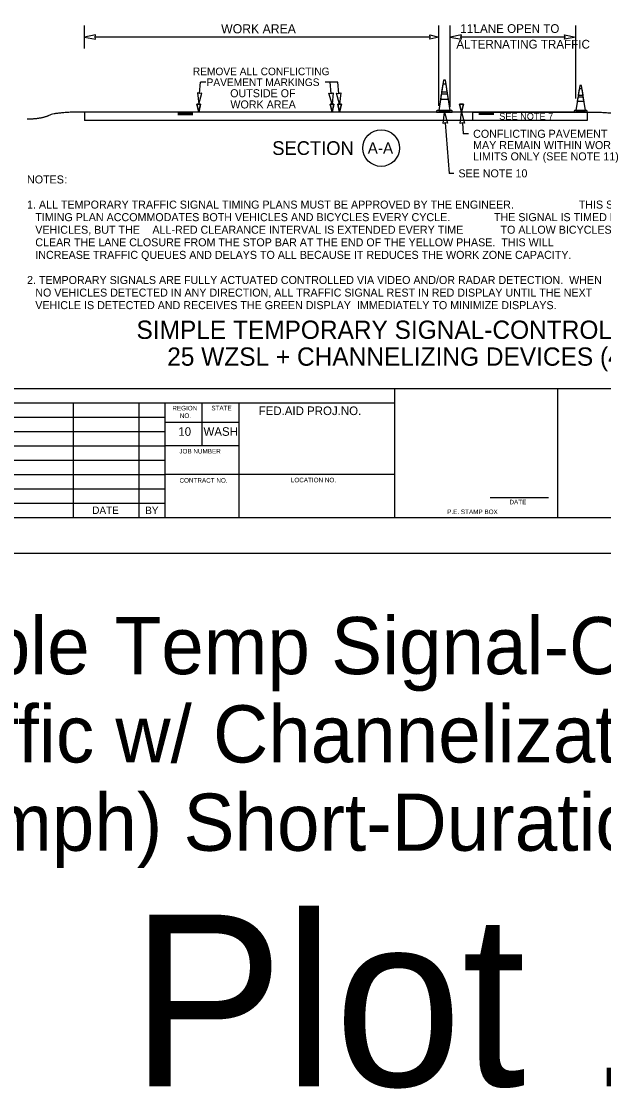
# Model space of a CAD drawing. Extents: x 99979.8 to 100075.7, y 99995 to 100010.7.
# Drawn here: x 100004.19 to 100009.28, y 99995.01 to 100004.34 of the extents above; entities that cross this region are included whole.
import ezdxf

# ---------------------------------------------------------------- set-up
doc = ezdxf.new("R2010")
doc.units = 0
for name, color, linetype in [('SH_DE_DetailHeading1Text', 7, 'Continuous'), ('SH_GI_GeneralNotesBodyText', 7, 'Continuous'), ('SH_GI_PlotLimits', 7, 'Continuous'), ('SH_GI_SheetBorder', 7, 'Continuous'), ('SH_GI_SheetLocationText', 7, 'Continuous'), ('SH_GI_SheetTextInCells', 7, 'Continuous'), ('TR_WZ_TrafficConeElev', 7, 'Continuous'), ('TR_WZ_WorkZoneDetails', 7, 'Continuous'), ('TR_WZ_WorkZoneTextCurrent', 7, 'Continuous')]:
    doc.layers.add(name, color=color, linetype=linetype)

msp = doc.modelspace()

# ---------------------------------------------------------------- linework, layer by layer
at = {"layer": 'SH_GI_PlotLimits'}
msp.add_lwpolyline([(99999.0625, 99999.6875), (100016.0625, 99999.6875), (100016.0625, 100010.6875), (99999.0625, 100010.6875)], close=True, dxfattribs=at)
at = {"layer": 'SH_GI_SheetBorder'}
for p, q in [((100000, 100001.1259), (100015.75, 100001.1259)), ((100007.4566, 100000), (100007.4566, 100001.1259)), ((100008.8828, 100000), (100008.8828, 100001.1259)), ((100000, 100001.0008), (100007.4566, 100001.0008)), ((100004.641, 100001.0008), (100004.641, 100000)), ((100005.2164, 100001.0008), (100005.2164, 100000)), ((100005.4451, 100001.0008), (100005.4451, 100000)), ((100005.7719, 100000.6255), (100005.7719, 100001.0008)), ((100006.0956, 100000), (100006.0956, 100001.0008)), ((100002.1821, 100000.8757), (100005.4466, 100000.8757)), ((100006.0958, 100000.831), (100005.4466, 100000.831)), ((100002.1821, 100000.7506), (100005.4466, 100000.7506)), ((100000, 100000.6255), (100005.4466, 100000.6255)), ((100006.0958, 100000.6255), (100005.4466, 100000.6255)), ((100000, 100000.5004), (100005.4466, 100000.5004)), ((100000, 100000.3753), (100005.4466, 100000.3753)), ((100007.4566, 100000.3753), (100005.4466, 100000.3753)), ((100000, 100000.2502), (100005.4466, 100000.2502)), ((100000, 100000.1251), (100005.4466, 100000.1251)), ((100008.2903, 100000.1733), (100008.802, 100000.1733)), ((100000, 100000), (100015.75, 100000))]:
    msp.add_line(p, q, dxfattribs=at)
at = {"layer": 'TR_WZ_TrafficConeElev'}
for p, q in [((100007.8754, 100003.7863), (100007.8655, 100003.7213)), ((100007.9057, 100003.7863), (100007.8754, 100003.7863)), ((100007.9156, 100003.7213), (100007.9057, 100003.7863)), ((100007.8624, 100003.7013), (100007.8555, 100003.6563)), ((100007.9187, 100003.7013), (100007.8624, 100003.7013)), ((100007.8655, 100003.7213), (100007.9156, 100003.7213)), ((100007.9256, 100003.6563), (100007.9187, 100003.7013)), ((100009.0592, 100003.6751), (100009.0535, 100003.6376)), ((100009.1062, 100003.6751), (100009.0592, 100003.6751)), ((100009.0701, 100003.7459), (100009.0618, 100003.6918)), ((100009.0618, 100003.6918), (100009.1036, 100003.6918)), ((100009.0953, 100003.7459), (100009.0701, 100003.7459)), ((100009.1036, 100003.6918), (100009.0953, 100003.7459)), ((100009.1119, 100003.6376), (100009.1062, 100003.6751)), ((100007.8555, 100003.6563), (100007.9256, 100003.6563)), ((100009.0535, 100003.6376), (100009.1119, 100003.6376)), ((100007.8262, 100003.5588), (100007.8212, 100003.5538)), ((100007.8212, 100003.5538), (100007.8212, 100003.5438)), ((100007.8212, 100003.5438), (100007.9599, 100003.5438)), ((100007.8405, 100003.5588), (100007.8262, 100003.5588)), ((100007.9599, 100003.5538), (100007.9549, 100003.5588)), ((100007.9599, 100003.5438), (100007.9599, 100003.5538)), ((100009.0291, 100003.5563), (100009.0249, 100003.5522)), ((100009.0249, 100003.5522), (100009.0249, 100003.5438)), ((100009.0249, 100003.5438), (100009.1405, 100003.5438)), ((100009.041, 100003.5563), (100009.0291, 100003.5563)), ((100009.1405, 100003.5522), (100009.1363, 100003.5563)), ((100009.1405, 100003.5438), (100009.1405, 100003.5522))]:
    msp.add_line(p, q, dxfattribs=at)
for points in [[(100007.8405, 100003.5588), (100007.9405, 100003.5588), (100007.8999, 100003.8238), (100007.8812, 100003.8238)], [(100007.8405, 100003.5588), (100007.9405, 100003.5588), (100007.8999, 100003.8238), (100007.8812, 100003.8238)], [(100009.041, 100003.5563), (100009.1244, 100003.5563), (100009.0905, 100003.7772), (100009.0749, 100003.7772)], [(100009.041, 100003.5563), (100009.1244, 100003.5563), (100009.0905, 100003.7772), (100009.0749, 100003.7772)]]:
    msp.add_lwpolyline(points, close=True, dxfattribs=at)
for points in [[(100007.9549, 100003.5588), (100007.9405, 100003.5588), (100007.8405, 100003.5588)], [(100009.1363, 100003.5563), (100009.1244, 100003.5563), (100009.041, 100003.5563)]]:
    msp.add_lwpolyline(points, dxfattribs=at)
at = {"layer": 'TR_WZ_WorkZoneDetails'}
for p, q in [((100004.7405, 100004.0999), (100004.7405, 100004.2999)), ((100007.8405, 100003.5988), (100007.8405, 100004.2999)), ((100007.9405, 100003.5888), (100007.9405, 100004.2999)), ((100009.0405, 100003.6636), (100009.0405, 100004.2999)), ((100007.7656, 100004.1999), (100004.8342, 100004.1999)), ((100008.9468, 100004.1999), (100008.0343, 100004.1999)), ((100005.7479, 100003.7071), (100005.7557, 100003.8046)), ((100005.8018, 100003.8046), (100005.7557, 100003.8046)), ((100006.9586, 100003.8046), (100006.8458, 100003.8046)), ((100006.8997, 100003.7071), (100006.8919, 100003.8046)), ((100006.9664, 100003.7071), (100006.9586, 100003.8046)), ((100004.7405, 100003.5438), (100004.7405, 100003.4688)), ((100009.1405, 100003.5438), (100004.7405, 100003.5438)), ((100005.5575, 100003.5386), (100005.6905, 100003.5386)), ((100005.5575, 100003.533), (100005.6905, 100003.533)), ((100005.5575, 100003.5273), (100005.6905, 100003.5273)), ((100005.5575, 100003.5221), (100005.6905, 100003.5221)), ((100008.3235, 100003.5382), (100008.1905, 100003.5382)), ((100008.3235, 100003.5326), (100008.1905, 100003.5326)), ((100008.3235, 100003.5269), (100008.1905, 100003.5269)), ((100008.3235, 100003.5217), (100008.1905, 100003.5217)), ((100009.1405, 100003.5438), (100009.1405, 100003.4688)), ((100009.1405, 100003.4688), (100004.7405, 100003.4688)), ((100007.898, 100003.4504), (100007.9333, 100003.0068)), ((100008.048, 100003.4504), (100008.0557, 100003.3528)), ((100008.1019, 100003.3528), (100008.0557, 100003.3528)), ((100007.9733, 100003.0068), (100007.9333, 100003.0068))]:
    msp.add_line(p, q, dxfattribs=at)
for points in [[(100004.7405, 100004.1999), (100004.8388, 100004.1806), (100004.8342, 100004.1999), (100004.8388, 100004.2192)], [(100007.8405, 100004.1999), (100007.7619, 100004.1806), (100007.7656, 100004.1999), (100007.7619, 100004.2192)], [(100007.9405, 100004.1999), (100008.0388, 100004.1806), (100008.0343, 100004.1999), (100008.0388, 100004.2192)], [(100009.0405, 100004.1999), (100008.9423, 100004.1806), (100008.9468, 100004.1999), (100008.9423, 100004.2192)], [(100005.7405, 100003.6136), (100005.7674, 100003.7101), (100005.7479, 100003.7071), (100005.729, 100003.7131)], [(100006.9071, 100003.6136), (100006.8802, 100003.7101), (100006.8998, 100003.7071), (100006.9186, 100003.7131)], [(100006.9738, 100003.6136), (100006.9469, 100003.7101), (100006.9665, 100003.7071), (100006.9853, 100003.7131)], [(100005.7405, 100003.5438), (100005.7238, 100003.6136), (100005.7572, 100003.6136)], [(100006.9072, 100003.5438), (100006.8905, 100003.6136), (100006.9238, 100003.6136)], [(100006.9739, 100003.5438), (100006.9572, 100003.6136), (100006.9905, 100003.6136)], [(100008.0405, 100003.5438), (100008.0238, 100003.6136), (100008.0572, 100003.6136)], [(100007.8905, 100003.5438), (100007.9175, 100003.4474), (100007.8979, 100003.4504), (100007.8791, 100003.4443)], [(100008.0405, 100003.5438), (100008.0675, 100003.4474), (100008.0479, 100003.4504), (100008.0291, 100003.4443)], [(100008.1405, 100003.5438), (100009.1405, 100003.5438), (100009.1405, 100003.4688), (100008.1405, 100003.4688)], [(100008.1405, 100003.5438), (100009.1405, 100003.5438), (100009.1405, 100003.4688), (100008.1405, 100003.4688)]]:
    msp.add_lwpolyline(points, close=True, dxfattribs=at)
for points in [[(100005.7572, 100003.6136), (100005.7238, 100003.6136), (100005.7405, 100003.5438), (100005.7572, 100003.6136)], [(100006.9238, 100003.6136), (100006.8905, 100003.6136), (100006.9072, 100003.5438), (100006.9238, 100003.6136)], [(100006.9905, 100003.6136), (100006.9572, 100003.6136), (100006.9739, 100003.5438), (100006.9905, 100003.6136)], [(100008.0572, 100003.6136), (100008.0238, 100003.6136), (100008.0405, 100003.5438), (100008.0572, 100003.6136)]]:
    msp.add_lwpolyline(points, dxfattribs=at)
msp.add_circle((100007.3371, 100003.2289), 0.16, dxfattribs=at)
for points in [[(100004.7405, 100003.5438), (100004.4893, 100003.5438), (100004.3639, 100003.4817), (100004.2384, 100003.4817)], [(100009.1405, 100003.5438), (100009.3917, 100003.544), (100009.5172, 100003.4819), (100009.6427, 100003.482)]]:
    msp.add_open_spline(points, degree=2, dxfattribs=at)

# ---------------------------------------------------------------- texts
at = {"layer": 'SH_DE_DetailHeading1Text'}
for s, p in [('SIMPLE TEMPORARY SIGNAL-CONTROLLED ALTERNATING 1-LANE, 2-WAY TRAFFIC', (100005.196, 100001.5606)), ('25 WZSL + CHANNELIZING DEVICES (45+ MPH HIGHWAYS, 7 DAYS OR LESS)', (100005.4651, 100001.3259))]:
    msp.add_text(s, height=0.16, rotation=360, dxfattribs=at).set_placement(p)
at = {"layer": 'SH_GI_GeneralNotesBodyText'}
for s, p in [('NOTES', (100004.2384, 100002.9196)), (':', (100004.5659, 100002.9196)), ('1. ALL TEMPORARY TRAFFIC SIGNAL TIMING PLANS MUST BE APPROVED BY THE ENGINEER. ', (100004.2384, 100002.6998)), ('THIS SIGNAL ', (100009.0661, 100002.6998)), ('TIMING PLAN ACCOMMODATES BOTH VEHICLES AND BICYCLES EVERY CYCLE.', (100004.3106, 100002.5899)), ('  THE SIGNAL IS TIMED FOR ', (100008.272, 100002.5899)), ('VEHICLES, BUT THE ', (100004.3106, 100002.48)), ('ALL-RED CLEARANCE INTERVAL IS EXTENDED EVERY TIME', (100005.3354, 100002.48)), (' TO ALLOW BICYCLES TO ', (100008.3553, 100002.48)), ('CLEAR THE LANE CLOSURE FROM THE STOP BAR AT THE END OF THE YELLOW PHASE.  THIS WILL ', (100004.3106, 100002.3701)), ('INCREASE TRAFFIC QUEUES AND DELAYS TO ALL BECAUSE IT REDUCES THE WORK ZONE CAPACITY.', (100004.3106, 100002.2602)), ('2. TEMPORARY SIGNALS ARE FULLY ACTUATED CONTROLLED VIA VIDEO AND/OR RADAR DETECTION.  WHEN ', (100004.2384, 100002.0404)), ('NO VEHICLES DETECTED IN ANY DIRECTION, ALL TRAFFIC SIGNAL REST IN RED DISPLAY UNTIL THE NEXT ', (100004.3106, 100001.9305)), ('VEHICLE IS DETECTED AND RECEIVES THE GREEN DISPLAY  IMMEDIATELY TO MINIMIZE DISPLAYS.', (100004.3106, 100001.8206))]:
    msp.add_text(s, height=0.07, rotation=360, dxfattribs=at).set_placement(p)
at = {"layer": 'SH_GI_SheetLocationText'}
for s, height, p in [('Simple', 0.5, (100002.743, 99998.6291)), (' Temp Signal-Controlled', 0.5, (100004.8187, 99998.6291)), ('Alt Traffic w/ Channelization Devices', 0.5, (100002.0024, 99997.8571)), ('(45+ mph) Short-Duration Version', 0.5, (100002.356, 99997.0851)), ('Plot 1', 1.5, (100005.1448, 99995.0267))]:
    msp.add_text(s, height=height, dxfattribs=at).set_placement(p)
at = {"layer": 'SH_GI_SheetTextInCells'}
for s, height, p in [('REGION', 0.04003, (100005.5099, 100000.9352)), ('STATE', 0.04003, (100005.8511, 100000.9357)), ('FED.AID PROJ.NO.', 0.07506, (100006.2652, 100000.8945)), ('NO.', 0.04003, (100005.5752, 100000.869)), ('10', 0.07506, (100005.5621, 100000.7131)), ('WASH', 0.07506, (100005.7826, 100000.7131)), ('JOB NUMBER', 0.04003, (100005.5712, 100000.5587)), ('CONTRACT NO.', 0.040032, (100005.5725, 100000.3037)), ('LOCATION NO.', 0.040032, (100006.5465, 100000.3067)), ('DATE', 0.04003, (100008.4597, 100000.1141)), ('DATE', 0.06505, (100004.8091, 100000.03)), ('BY', 0.06505, (100005.2725, 100000.0285)), ('P.E. STAMP BOX', 0.040032, (100007.915, 100000.0286))]:
    msp.add_text(s, height=height, dxfattribs=at).set_placement(p)
at = {"layer": 'TR_WZ_WorkZoneDetails'}
for s, height, p in [('WORK AREA', 0.08, (100005.937, 100004.2319)), ("11'", 0.076, (100008.0294, 100004.2359)), (' LANE OPEN TO', 0.076, (100008.1174, 100004.2359)), ('ALTERNATING TRAFFIC', 0.076, (100007.9949, 100004.0991))]:
    msp.add_text(s, height=height, dxfattribs=at).set_placement(p)
for s, height, p in [('SECTION', 0.12, (100006.384, 100003.1689)), ('A-A', 0.1, (100007.2192, 100003.1789))]:
    msp.add_text(s, height=height, rotation=360, dxfattribs=at).set_placement(p)
at = {"layer": 'TR_WZ_WorkZoneTextCurrent'}
for s, height, p in [('REMOVE ALL CONFLICTING', 0.0665, (100005.6895, 100003.8659)), ('PAVEMENT MARKINGS', 0.0665, (100005.8095, 100003.7714)), ('OUTSIDE OF', 0.07, (100006.016, 100003.6734)), ('WORK AREA', 0.07, (100006.018, 100003.5754)), ('SEE NOTE 7', 0.06, (100008.3705, 100003.4763)), ('CONFLICTING PAVEMENT MARKING', 0.07, (100008.1419, 100003.3188)), ('MAY REMAIN WITHIN WORK AREA', 0.07, (100008.1419, 100003.22)), ('LIMITS ONLY (SEE NOTE 11)', 0.07, (100008.1419, 100003.1212)), ('SEE NOTE 10', 0.07, (100008.0133, 100002.9728))]:
    msp.add_text(s, height=height, dxfattribs=at).set_placement(p)

doc.saveas('drawing.dxf')
